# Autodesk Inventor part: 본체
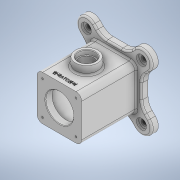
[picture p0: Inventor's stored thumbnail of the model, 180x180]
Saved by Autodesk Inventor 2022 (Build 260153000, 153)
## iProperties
Created: 2022-05
Part Number: 본체
Material: 일반
Document SubType Name: Modeling
Designer: admin
Density: 1 g/cm^3
Appearance: 기본값
Author: admin
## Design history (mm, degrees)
sketch "스케치1" dims "d4" = 140
  geometry: L1 (-122.868, 0)-(107.923, 0) reference; L2 (0, -107.923)-(0, 122.868) reference; L3 (-49, 0)-(-49, 23.544); L4 (-49, 49)-(0, 49); L5 (0, 0)-(-89.897, 89.897); L6 (-49.497, 49.497)-(-25.81, 73.185); L7 (-49.497, 49.497)-(-70, 28.995); L8 (-36.77, 62.225)-(-23.544, 49); L9 (-62.225, 36.77)-(-49, 23.544); L10 (0, 49)-(-23.544, 49); L11 (-62.225, -36.77)-(-49, -23.544); L12 (-36.77, -62.225)-(-23.544, -49); L13 (0, -49)-(-23.544, -49); L14 (-49, 0)-(-49, -23.544); L15 (36.77, -62.225)-(23.544, -49); L16 (62.225, -36.77)-(49, -23.544); L17 (49, 0)-(49, -23.544); L18 (0, -49)-(23.544, -49); L19 (62.225, 36.77)-(49, 23.544); L20 (36.77, 62.225)-(23.544, 49); L21 (0, 49)-(23.544, 49); L22 (49, 0)-(49, 23.544); C1 r 5 at (-49.497, 49.497); C2 r 5 at (-49.497, -49.497); C3 r 5 at (49.497, -49.497); C4 r 5 at (49.497, 49.497); A1 r 18 centre (-49.497, 49.497) between (-36.77, 62.225) and (-62.225, 36.77); A2 r 18 centre (-49.497, -49.497) between (-62.225, -36.77) and (-36.77, -62.225); A3 r 18 centre (49.497, -49.497) between (36.77, -62.225) and (62.225, -36.77); A4 r 18 centre (49.497, 49.497) between (62.225, 36.77) and (36.77, 62.225); 5 further points
  constraints: 40 end point, 8 centre point, 8 point on circle, 7 point on line, 5 coincident, 3 perpendicular, 1 parallel, 1 tangent, 1 vertical, 62 other
  dimensions: "d0" = 49 distance of L4.start L4.end; "d1" = 49 distance of L3.start L4.start; "d2" = 45 deg angle of L2 L5; "d3" = 36 diameter of A1; "d5" = 49 distance between parallel lines of L1 L4; "d6" = 10 diameter of C1; "d9" = 360 deg dimension on point (0, 0) L6.start (derived)
extrude "돌출1" new body sketch "스케치1" distance "d11" = 12; taper "d12" = 0 deg
sketch "스케치2"
  geometry: L1 (-94.496, 0)-(94.496, 0) reference; L2 (0, -94.496)-(0, 94.496) reference; C1 r 5 at (-49.497, 49.497) reference; C2 r 9 at (-49.497, 49.497); C3 r 9 at (49.497, 49.497); C4 r 9 at (-49.497, -49.497); C5 r 9 at (49.497, -49.497); 1 further point
  constraints: 4 centre point, 3 symmetric about line, 1 coincident, 3 other
  dimensions: "d13" = 18 diameter of C2
extrude "돌출2" cut sketch "스케치2" distance "d14" = 4; taper "d15" = 0 deg
sketch "스케치3"
  geometry: L1 (-40, -40)-(40, -40); L2 (40, -40)-(40, 40); L3 (40, 40)-(-40, 40); L4 (-40, 40)-(-40, -40); L5 (-40, -40)-(40, 40); L6 (40, -40)-(-40, 40); 1 further point
  constraints: 12 end point, 2 midpoint, 2 parallel, 1 horizontal, 1 perpendicular
  dimensions: "d16" = 80 distance of L2.end L3.end; "d17" = 80 distance of L1.end L2.end
extrude "돌출3" join sketch "스케치3" distance "d18" = 98; taper "d19" = 0 deg
sketch "스케치4"
  geometry: C1 r 25 at (0, 0); 1 further point
  constraints: 1 centre point, 1 coincident
  dimensions: "d20" = 50 diameter of C1
extrude "돌출4" cut sketch "스케치4" extent not by distance; stored distance "d21" = 0; taper "d22" = 0 deg
node "작업 평면1"
sketch "스케치5"
  geometry: C1 r 35 at (0, 0); 1 further point
  constraints: 1 centre point, 1 coincident
  dimensions: "d24" = 70 diameter of C1
extrude "돌출5" cut sketch "스케치5" distance "d25" = 86; taper "d26" = 0 deg
sketch "스케치6"
  geometry: L1 (63.544, 0)-(16.456, 0) reference; L2 (0, 0)-(0, -98) reference; C1 r 20 at (40, -49); 1 further point
  constraints: 1 centre point
  dimensions: "d27" = 40 diameter of C1; "d28" = 49 distance from line of L1 C1.centre; "d29" = 40 distance from line of C1.centre L2
extrude "돌출6" join sketch "스케치6" distance "d30" = 15; taper "d31" = 0 deg
sketch "스케치7"
  geometry: L1 (0, 83)-(0, -71) reference; L2 (23.544, 49)-(-23.544, 49) reference; C1 r 12.5 at (0, 0); 1 further point
  constraints: 1 centre point, 1 point on line
  dimensions: "d32" = 25 diameter of C1; "d33" = 49 distance from line of L2 C1.centre
extrude "돌출7" cut sketch "스케치7" stored distance "d34" = 15; taper "d35" = 0 deg
sketch "스케치8"
  geometry: L1 (23.544, 49)-(-23.544, 49) reference; L2 (-40, 49)-(-40, -49) reference; C1 r 15 at (0, 0); 1 further point
  constraints: 1 centre point
  dimensions: "d36" = 30 diameter of C1; "d37" = 49 distance from line of L1 C1.centre; "d38" = 40 distance from line of L2 C1.centre
extrude "돌출8" cut sketch "스케치8" distance "d39" = 8; taper "d40" = 0 deg
sketch "스케치9"
  geometry: L1 (80, -98)-(0, -98) reference; L2 (80, 0)-(80, -98) reference; 2 further points
  constraints: 1 other
  dimensions: "d41" = 10 distance from line of L1 point (40, -88); "d42" = 40 distance from line of L2 point (40, -88)
feature "엠보싱1" sketch "스케치9" dims "d43" = 0.5, "d44" = 0
sketch "스케치10"
  geometry: L1 (-30, -30)-(30, -30); L2 (30, -30)-(30, 30); L3 (30, 30)-(-30, 30); L4 (-30, 30)-(-30, -30); L5 (-30, -30)-(30, 30); L6 (30, -30)-(-30, 30); 5 further points
  constraints: 12 end point, 4 coincident, 2 midpoint, 2 parallel, 1 horizontal, 1 perpendicular
  dimensions: "d45" = 60 distance of L3.end L2.end; "d46" = 60 distance of L2.end L1.end
hole "구멍1" sketch "스케치10" at (-30, 30), (30, 30), (30, -30), (-30, -30) diameter "d47" = 3.242; stored, may be unused: countersink angle "d51" = 90 deg, drill point angle "d53" = 118 deg; dims "d48" = 8, "d49" = 4, "d50" = 2, "d52" = 10
fillet "모깎기1" dims "d54" = 10
fillet "모깎기2" dims "d55" = 25
fillet "모깎기3" dims "d56" = 3
chamfer "모따기1" distance "d57" = 1; stored, may be unused: second distance "d58" = 2, angle "d59" = 45 deg
fillet "모깎기4" dims "d60" = 3
sketch "스케치11"
  geometry: C1 r 1.621 at (-30, 30) reference; C2 r 1.621 at (30, 30) reference; C3 r 1.621 at (30, -30) reference; C4 r 1.621 at (-30, -30) reference; 5 further points
  constraints: 4 coincident
hole "구멍2" sketch "스케치11" at (-30, 30), (30, 30), (30, -30), (-30, -30) diameter "d61" = 3.242; stored, may be unused: countersink angle "d65" = 90 deg, drill point angle "d67" = 118 deg; dims "d62" = 8, "d63" = 4, "d64" = 2, "d66" = 10
node "솔리드1"
feature "A9D066F2-1C7D-4E18-AEED-F7BC21143FA4" dims "d47" = 3.242, "d48" = 8, "d49" = 4, "d50" = 2, "d51" = 90 deg, "d52" = 10, "d53" = 118 deg
other parameters: "d23" = -12
